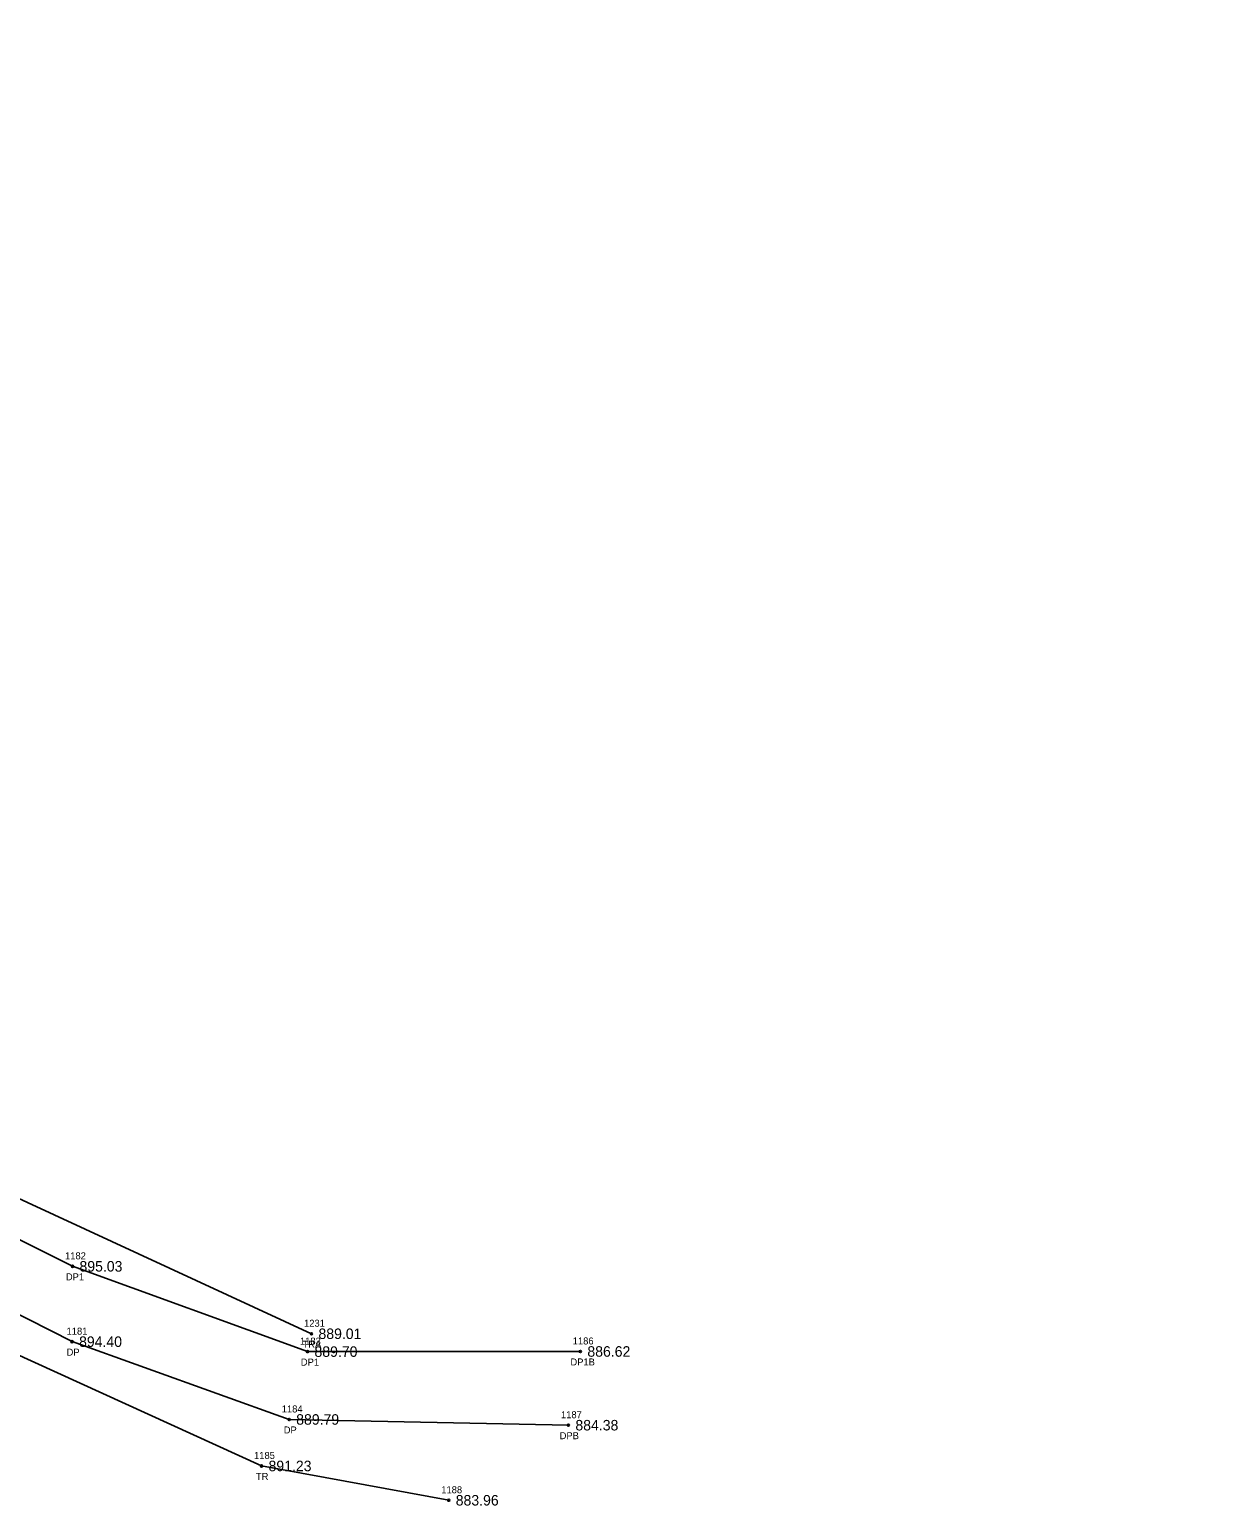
# Model space of a CAD drawing. Extents: x 1393163 to 1398407, y 1072670 to 1074651.
# Drawn here: x 1396969.4 to 1397140.6, y 1074266.9 to 1074477.8 of the extents above; entities that cross this region are included whole.
import ezdxf

# ---------------------------------------------------------------- set-up
doc = ezdxf.new("R2010")
doc.units = 0
for name, color, linetype in [('RD_EX_Driveway', 7, 'Continuous'), ('RD_EX_Driveway_txCode', 7, 'Continuous'), ('RD_EX_TX_Driveway_ELEV', 7, 'Continuous'), ('RD_EX_TX_VEG_ELEV', 7, 'Continuous'), ('RD_EX_VEG', 7, 'Continuous'), ('RD_EX_VEG_txCode', 7, 'Continuous'), ('RD_SMD_Locator', 7, 'Continuous')]:
    doc.layers.add(name, color=color, linetype=linetype)

msp = doc.modelspace()

# ---------------------------------------------------------------- linework, layer by layer
at = {"layer": 'RD_EX_Driveway'}
for points in [[(1396788.75, 1074345.97), (1396814, 1074347.19), (1396845.44, 1074351.21), (1396872.44, 1074348.53), (1396900.89, 1074337.89), (1396935.17, 1074321.37), (1396975.52, 1074301.17), (1397009.08, 1074288.99), (1397048.05, 1074289.01)], [(1396826.71, 1074324.07), (1396825.97, 1074333.3), (1396831.82, 1074338.86), (1396844.73, 1074340.58), (1396868.8, 1074338.53), (1396897.2, 1074328.86), (1396931.55, 1074312.72), (1396975.46, 1074290.41), (1397006.47, 1074279.3), (1397046.34, 1074278.48)]]:
    msp.add_lwpolyline(points, dxfattribs=at)
at = {"layer": 'RD_EX_VEG'}
for points in [[(1397009.65, 1074291.54), (1396903.78, 1074340.47), (1396857.31, 1074355.57), (1396838.07, 1074357.65), (1396801.02, 1074382.43), (1396783.06, 1074391.67), (1396723.05, 1074425.5), (1396738.49, 1074477.8)], [(1397153.93, 1074137.81), (1397083.5, 1074191.3), (1396998.48, 1074234.23), (1396876.65, 1074321.33), (1396895.14, 1074321.61), (1397002.52, 1074272.66), (1397029.25, 1074267.76)]]:
    msp.add_lwpolyline(points, dxfattribs=at)
at = {"layer": 'RD_SMD_Locator'}
for centre in [(1396975.52, 1074301.17), (1397009.65, 1074291.54), (1396975.46, 1074290.41), (1397009.08, 1074288.99), (1397048.05, 1074289.01), (1397006.47, 1074279.3), (1397046.34, 1074278.48), (1397002.52, 1074272.66), (1397029.25, 1074267.76)]:
    msp.add_circle(centre, 0.15, dxfattribs=at)

# ---------------------------------------------------------------- texts
at = {"layer": 'RD_EX_Driveway_txCode'}
for s, p in [('1182', (1396974.46, 1074302.17)), ('DP1', (1396974.58, 1074299.17)), ('1181', (1396974.68, 1074291.41)), ('DP', (1396974.68, 1074288.41)), ('1183', (1397008.01, 1074289.99)), ('1186', (1397046.96, 1074290.01)), ('DP1', (1397008.13, 1074286.99)), ('DP1B', (1397046.63, 1074287.01)), ('1184', (1397005.41, 1074280.3)), ('1187', (1397045.28, 1074279.48)), ('DP', (1397005.69, 1074277.3)), ('DPB', (1397045.09, 1074276.48))]:
    msp.add_text(s, height=1, dxfattribs=at).set_placement(p)
at = {"layer": 'RD_EX_TX_Driveway_ELEV'}
for s, p in [('895.03', (1396976.52, 1074300.42)), ('894.40', (1396976.46, 1074289.66)), ('889.70', (1397010.08, 1074288.24)), ('886.62', (1397049.05, 1074288.26)), ('889.79', (1397007.47, 1074278.55)), ('884.38', (1397047.34, 1074277.73))]:
    msp.add_text(s, height=1.5, dxfattribs=at).set_placement(p)
at = {"layer": 'RD_EX_TX_VEG_ELEV'}
for s, p in [('889.01', (1397010.65, 1074290.79)), ('891.23', (1397003.52, 1074271.91)), ('883.96', (1397030.25, 1074267.01))]:
    msp.add_text(s, height=1.5, dxfattribs=at).set_placement(p)
at = {"layer": 'RD_EX_VEG_txCode'}
for s, p in [('1231', (1397008.59, 1074292.54)), ('TRA', (1397008.37, 1074289.54)), ('1185', (1397001.45, 1074273.66)), ('TR', (1397001.72, 1074270.66)), ('1188', (1397028.19, 1074268.76))]:
    msp.add_text(s, height=1, dxfattribs=at).set_placement(p)

doc.saveas('drawing.dxf')
